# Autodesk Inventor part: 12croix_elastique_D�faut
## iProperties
Created: 2011-01
Part Number: 12croix_elastique_D�faut
Document SubType Name: Modeling
Designer: eric
Density: 1 g/cm^3
Mass: 0.878715 g
Surface Area: 8.99989 cm^2
Volume: 0.878715 cm^3
Author: eric
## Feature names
1. Base1
